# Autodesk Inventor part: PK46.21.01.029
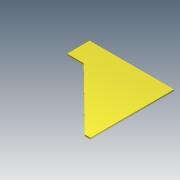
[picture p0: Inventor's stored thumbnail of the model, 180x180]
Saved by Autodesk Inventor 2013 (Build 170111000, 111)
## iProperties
Created: 2005-04
Part Number: PK46.21.01.029
Material: Steel, Mild
Document SubType Name: Modeling
Designer: salex
Manufacturer: Standard
Standards Organization: Custom
Density: 7.86 g/cm^3
Author: salex
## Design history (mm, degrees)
sketch "Эскиз1"
  geometry: L1 (0, 0)-(0, 163); L2 (0, 163)-(610, 163); L3 (610, 163)-(610, -442); L4 (610, -442)-(570, -442); L5 (570, -442)-(120, 0); L6 (120, 0)-(0, 0)
  constraints: 12 end point, 3 parallel, 1 perpendicular, 1 vertical, 1 other
  dimensions: "d0" = 610 distance between parallel lines of L3 L1; "d3" = 605 distance between parallel lines of L2 L4; "d7" = 40 distance of L3.end L4.end; "d8" = 490 distance from line of L5.end L3; "d9" = 442 distance between parallel lines of L6 L4
extrude "Выдавливание1" new body sketch "Эскиз1" distance "d5" = 10; taper "d6" = 0 deg
body "Solid1"
